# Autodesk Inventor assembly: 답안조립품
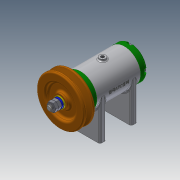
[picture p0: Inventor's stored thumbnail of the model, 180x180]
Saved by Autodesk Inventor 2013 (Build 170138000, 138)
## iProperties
Created: 2020-07
Part Number: 답안조립품
Document SubType Name: Assembly
Designer: 88
Author: 88
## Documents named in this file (15)
- C:\Users\88\Documents\Inventor\700706V1034\답안조립품.iam
- C:\Users\88\Documents\Inventor\700706V1034\본체.ipt
- C:\Users\88\Documents\Inventor\700706V1034\700706V1034\V벨트풀리.ipt
- C:\Users\88\Documents\Inventor\700706V1034\700706V1034\너트 M8.ipt
- C:\Users\88\Documents\Inventor\700706V1034\700706V1034\뒤커버.ipt
- C:\Users\88\Documents\Inventor\700706V1034\700706V1034\베어링 6002.ipt
- C:\Users\88\Documents\Inventor\700706V1034\700706V1034\볼트 M4x12.ipt
- C:\Users\88\Documents\Inventor\700706V1034\700706V1034\볼트 M6x8.ipt
- C:\Users\88\Documents\Inventor\700706V1034\700706V1034\스프링와셔 8.ipt
- C:\Users\88\Documents\Inventor\700706V1034\700706V1034\앞커버.ipt
- C:\Users\88\Documents\Inventor\700706V1034\700706V1034\오일 실 15 25 7.ipt
- C:\Users\88\Documents\Inventor\700706V1034\700706V1034\와셔 6x11.5.ipt
- C:\Users\88\Documents\Inventor\700706V1034\700706V1034\와셔 8x17.ipt
- C:\Users\88\Documents\Inventor\700706V1034\700706V1034\축.ipt
- C:\Users\88\Documents\Inventor\700706V1034\700706V1034\키 3x3x12.ipt
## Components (1 placed, 1 different names)
1. V벨트풀리:1 — 각도:4
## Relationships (1: Angle 1)
- 각도:4 [Angle]: V벨트풀리:1
